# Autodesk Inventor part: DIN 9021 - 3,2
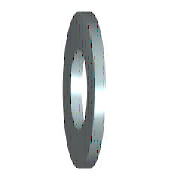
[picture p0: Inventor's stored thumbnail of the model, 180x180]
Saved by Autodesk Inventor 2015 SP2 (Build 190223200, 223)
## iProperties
Created: 2012-02
Part Number: DIN 9021 - 3,2
Material: Stahl, weich
Description: Unterlegscheibe
Document SubType Name: Modeling
Standard: DIN 9021
Designer: Hübner
Standards Organization: DIN
Language: de-DE
Size Designation: 3,2
Categories: <MemberInstance><Categories><Category DisplayName="Verbindungselemente" InternalName="e4da775c-781d-43d5-af7c-5136215cf5a6" Mnemonic="FSTN"><Category DisplayNam
Density: 7.85 g/cm^3
Appearance: Halbpoliert
Mass: 0.34901 g
Surface Area: 1.41811 cm^2
Volume: 0.0444598 cm^3
IsCustomPart: 0
Author: Hübner
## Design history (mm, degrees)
sketch "Skizze"
  geometry: C1 r 4.5 at (0, 0); C2 r 1.6 at (0, 0); 1 further point
  constraints: 2 centre point, 2 coincident
  dimensions: "d0" = 3.2 diameter of C2 (= SD1); "d1" = 9 diameter of C1 (= SD2)
extrude "Körper" new body sketch "Skizze" distance "d2" = 0.8 (= SD); taper "d3" = 0 deg
workaxis "Work Axis1"
workplane "Work Plane1"
body "Solid1"
other parameters: "SD1" = 3.2 [user parameter; used in 1 equation term], "SD2" = 9 [user parameter; used in 1 equation term], "SD" = 0.8 [user parameter; used in 1 equation term], "d4" = 0, "d5" = 0, "d6" = 0, "d7" = 0, "NND" = 3 [user parameter]
